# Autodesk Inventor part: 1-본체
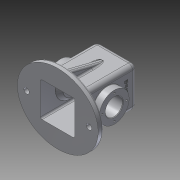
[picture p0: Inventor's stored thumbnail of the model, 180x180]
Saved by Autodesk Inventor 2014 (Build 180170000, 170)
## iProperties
Created: 2017-07
Part Number: 1-본체
Material: Aluminum 6061
Document SubType Name: Modeling
Designer: user
Density: 2.71 g/cm^3
Appearance: Aluminum - Flat
Author: user
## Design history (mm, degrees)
sketch "Sketch1" dims "d4" = 65, "d6" = 75
  geometry: 2 further points; 1 other entity
  constraints: 1 coincident, 2 other
extrude "Extrusion1" new body sketch "Sketch1" distance "d7" = 10; taper "d8" = 0 deg
sketch "Sketch2"
  geometry: L1 (-37, -37)-(37, -37); L2 (37, -37)-(37, 37); L3 (37, 37)-(-37, 37); L4 (-37, 37)-(-37, -37); L5 (-37, -37)-(37, 37); L6 (37, -37)-(-37, 37); 1 further point
  constraints: 12 end point, 2 midpoint, 2 parallel, 1 horizontal, 1 perpendicular
  dimensions: "d9" = 74 distance of L3.end L2.end; "d10" = 74 distance of L2.end L1.end
extrude "Extrusion2" join sketch "Sketch2" distance "d11" = 100; taper "d12" = 0 deg
sketch "Sketch3"
  geometry: L1 (-32, 105)-(32, 105); L2 (-32, 105)-(-32, 0); L3 (32, 105)-(32, 0); L4 (-32, 0)-(32, 0); L5 (37, 110)-(-37, 110) reference; 1 further point
  constraints: 8 end point, 3 parallel, 1 perpendicular
  dimensions: "d16" = 5 horizontal distance of L1.end L5.start; "d17" = 110 distance between parallel lines of L4 L5; "d18" = 64 distance between parallel lines of L3 L2; "d19" = 5 distance from line of L5.start L3
extrude "Extrusion3" cut sketch "Sketch3" stored distance "d20" = 64; taper "d21" = 0 deg
sketch "Sketch4"
  geometry: C1 r 27.5 at (37, 45); 1 further point
  constraints: 1 centre point, 1 vertical alignment
  dimensions: "d30" = 55 diameter of C1; "d31" = 55 distance of C1.centre point (37, -10)
extrude "Extrusion4" join sketch "Sketch4" distance "d32" = 13; taper "d33" = 0 deg
sketch "Sketch5"
  geometry: C1 r 27.5 at (37, 45); 1 further point
  constraints: 1 centre point, 1 vertical alignment
  dimensions: "d35" = 55 diameter of C1; "d36" = 55 distance of C1.centre point (37, -10)
extrude "Extrusion5" join sketch "Sketch5" distance "d37" = 13; taper "d38" = 0 deg
sketch "Sketch6"
  geometry: C1 r 27.5 at (0, 0) reference; C2 r 16 at (0, 0); 1 further point
  constraints: 1 centre point, 1 coincident
  dimensions: "d39" = 32 diameter of C2
extrude "Extrusion6" cut sketch "Sketch6" stored distance "d40" = 13; taper "d41" = 0 deg
sketch "Sketch7"
  geometry: L1 (50, 82.5)-(32, 82.5); L2 (32, 82.5)-(25, 75.5); L3 (32, 82.5)-(41.899, 82.5); L4 (25, 75.5)-(25, 55); L5 (25, 55)-(50, 55); L6 (50, 82.5)-(50, 55); 1 further point
  constraints: 12 end point, 2 perpendicular, 1 equal length, 1 horizontal, 1 vertical
  dimensions: "d49" = 135 deg angle of L2 L3; "d50" = 7 horizontal distance of L1.end L2.end; "d51" = 55 vertical distance of point (0, 0) L4.end; "d52" = 90 deg angle of L6 L1; "d55" = 25 horizontal distance of L1.start L2.end
revolve "Revolution1" sketch "Sketch7" stored, may be unused: angle "d54" = 90 deg
sketch "Sketch8"
  geometry: L1 (-50, 82.5)-(-32, 82.5); L2 (-32, 82.5)-(-25, 75.5); L3 (-25, 75.5)-(-25, 55); L4 (-50, 55)-(-25, 55); L5 (-50, 82.5)-(-50, 55); 1 further point
  constraints: 10 end point, 3 perpendicular, 1 vertical
  dimensions: "d63" = 7 horizontal distance of L1.end L2.end; "d64" = 135 deg angle of L2 L1; "d65" = 55 vertical distance of point (0, 0) L3.end; "d66" = 25 distance between parallel lines of L5 L3
revolve "Revolution2" sketch "Sketch8" stored, may be unused: angle "d67" = 90 deg
sketch "Sketch9"
  geometry: C1 r 27.5 at (0, 0) reference; C2 r 16 at (0, 0); 1 further point
  constraints: 1 centre point, 1 coincident
  dimensions: "d68" = 32 diameter of C2
extrude "Extrusion7" cut sketch "Sketch9" stored distance "d69" = 13; taper "d70" = 0 deg
workplane "Work Plane1"
sketch "Sketch10"
  geometry: L1 (20, -20)-(-20, -20); L2 (-20, -20)-(-20, 20); L3 (-20, 20)-(20, 20); L4 (20, 20)-(20, -20); L5 (20, -20)-(-20, 20); L6 (-20, -20)-(20, 20); 1 further point
  constraints: 12 end point, 2 midpoint, 2 parallel, 1 horizontal, 1 perpendicular
  dimensions: "d72" = 40 distance of L2.end L3.end; "d73" = 40 distance of L1.end L2.end
extrude "Extrusion8" join sketch "Sketch10" stored distance "d74" = 13; taper "d75" = 0 deg
sketch "Sketch11"
  geometry: C1 r 14 at (0, 0); 1 further point
  constraints: 1 centre point, 1 coincident
  dimensions: "d76" = 28 diameter of C1
extrude "Extrusion9" cut sketch "Sketch11" distance "d77" = 4; taper "d78" = 0 deg
sketch "Sketch12"
  geometry: C1 r 10.5 at (0, 0); 1 further point
  constraints: 1 centre point, 1 coincident
  dimensions: "d79" = 21 diameter of C1
extrude "Extrusion10" cut sketch "Sketch12" distance "d80" = 50; taper "d81" = 0 deg
feature "FaceDraft1" dims angle "d82" = 5 deg
sketch "Sketch13"
  geometry: C1 r 27.5 at (0, 0) reference; 5 further points
  dimensions: "d84" = 59.42432 distance of point (0, -55) point (22.5, 0); "d85" = 77.5 distance of point (0, -55) point (0, 22.5); "d86" = 32.5 distance of point (0, -55) point (0, -22.5); "d87" = 59.42432 distance of point (0, -55) point (-22.5, 0); "d88" = 31.81981 distance of point (22.5, 0) point (0, 22.5); "d89" = 31.81981 distance of point (22.5, 0) point (0, -22.5); "d90" = 45 distance of point (22.5, 0) point (-22.5, 0); "d91" = 22.5 distance of C1.centre point (22.5, 0)
hole "Hole1" sketch "Sketch13" at (0, 22.5), (22.5, 0), (0, -22.5), (-22.5, 0) diameter "d92" = 3.242; stored, may be unused: countersink angle "d96" = 90 deg, drill point angle "d98" = 118 deg; dims "d93" = 8, "d94" = 4, "d95" = 2, "d97" = 10
sketch "Sketch14"
  geometry: C1 r 27.5 at (0, 0) reference; 5 further points
  dimensions: "d100" = 22.5 distance of C1.centre point (22.5, 0); "d101" = 59.42432 distance of point (0, -55) point (22.5, 0); "d102" = 22.5 distance of C1.centre point (0, 22.5); "d103" = 77.5 distance of point (0, -55) point (0, 22.5); "d104" = 22.5 distance of C1.centre point (0, -22.5); "d105" = 22.5 distance of C1.centre point (-22.5, 0); "d106" = 32.5 distance of point (0, -55) point (0, -22.5); "d107" = 59.42432 distance of point (0, -55) point (-22.5, 0)
hole "Hole2" sketch "Sketch14" at (0, 22.5), (-22.5, 0), (0, -22.5), (22.5, 0) diameter "d108" = 3.242; stored, may be unused: countersink angle "d112" = 90 deg, drill point angle "d114" = 118 deg; dims "d109" = 8, "d110" = 4, "d111" = 2, "d113" = 10
sketch "Sketch15"
  geometry: C1 r 5 at (58, 0); C2 r 5 at (-58, 0); 1 further point
  constraints: 2 centre point, 2 horizontal alignment
  dimensions: "d116" = 10 diameter of C1; "d119" = 10 diameter of C2; "d120" = 116 distance of C1.centre C2.centre; "d121" = 58 distance of C1.centre point (0, 0)
extrude "Extrusion11" cut sketch "Sketch15" distance "d122" = 50; taper "d123" = 0 deg
sketch "Sketch17"
  geometry: L1 (82.194, 37)-(10, 55); L2 (82.194, 37)-(10, 37); L3 (10, 37)-(10, 55); 1 further point
  constraints: 6 end point, 1 horizontal, 1 perpendicular
  dimensions: "d133" = 14 deg angle of L1 L2; "d134" = 18 distance of L1.end L2.end; "d135" = 37 distance from line of point (0, 0) L2; "d136" = 55.78548 distance from line of point (0, 0) L1
extrude "Extrusion12" join sketch "Sketch17" stored distance "d137" = 10; taper "d138" = 0 deg
mirror "Mirror1"
chamfer "Chamfer1" distance "d139" = 1; stored, may be unused: second distance "d140" = 2, angle "d141" = 45 deg
chamfer "Chamfer2" distance "d142" = 1; stored, may be unused: second distance "d143" = 2, angle "d144" = 45 deg
fillet "Fillet1" dims "d145" = 8, "d146" = 0.5, "d147" = 3
sketch "Sketch18"
  geometry: L1 (-12, 107)-(-9, 107) reference; L2 (8, 0)-(8, 89) reference; 2 further points
  constraints: 1 other
  dimensions: "d150" = 30 distance from line of point (-29, 77) L1; "d151" = 37 distance from line of L2 point (-29, 77)
emboss "Emboss1" sketch "Sketch18" dims "d18" = 64, "d152" = 0.5, "d153" = 0
body "Solid1"
